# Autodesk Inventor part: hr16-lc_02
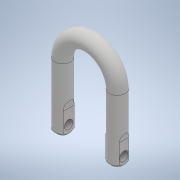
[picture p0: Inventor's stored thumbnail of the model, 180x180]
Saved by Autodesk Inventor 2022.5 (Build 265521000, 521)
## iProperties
Part Number: hr16-lc_02
Material: 一般
Document SubType Name: Modeling
Designer: ImaoCorp
Density: 1 g/cm^3
Appearance: 既定
Author: ImaoCorp
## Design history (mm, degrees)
feature "hr16-lc_02"
node "ソリッド1"
